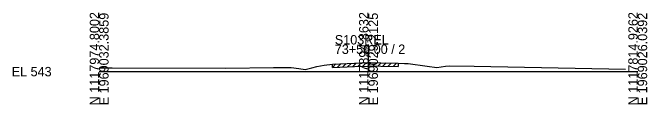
# Model space of a CAD drawing. Extents: x -26 to 163, y -10 to 24518.
# Drawn here: x -25.7 to 162.8, y 21990.3 to 22017.5 of the extents above; entities that cross this region are included whole.
import ezdxf

# ---------------------------------------------------------------- set-up
doc = ezdxf.new("R2010")
doc.units = 0
for name, color, linetype in [('RD_GPK_XS_Cell', 7, 'Continuous'), ('RD_XS_ExGround', 7, 'Continuous'), ('RD_XS_ExPaveRet', 7, 'Continuous'), ('RD_XS_TX_Elev_EX', 7, 'Continuous')]:
    doc.layers.add(name, color=color, linetype=linetype)

msp = doc.modelspace()

# ---------------------------------------------------------------- linework, layer by layer
at = {"layer": 'RD_GPK_XS_Cell'}
for p, q in [((80, 22000), (80, 22008.06)), ((0, 22000), (80, 22000)), ((80, 22000), (160, 22000))]:
    msp.add_line(p, q, dxfattribs=at)
at = {"layer": 'RD_XS_ExGround'}
msp.add_lwpolyline([(0, 22001.12), (3.84, 22001.13), (37.61, 22001.07), (51.79, 22001.2), (57, 22001.21), (59.27, 22000.93), (61.17, 22000.65), (63.13, 22001.14), (64.68, 22001.57), (66.82, 22001.89), (69.3, 22002.25), (75.84, 22002.5), (80, 22002.67), (80.5, 22002.69), (83.72, 22002.61), (88.78, 22002.52), (90.68, 22002.46), (91.83, 22002.42), (97.47, 22001.61), (100.33, 22001.2), (102.91, 22001.58), (104.22, 22001.74), (111.39, 22001.61), (156.35, 22000.78)], dxfattribs=at)
at = {"layer": 'RD_XS_ExPaveRet'}
for p, q in [((69.3, 22001.25), (70.34, 22002.29)), ((69.3, 22001.25), (69.3, 22002.25)), ((70.8, 22001.31), (71.84, 22002.35)), ((72.3, 22001.37), (73.34, 22002.41)), ((73.8, 22001.42), (74.84, 22002.46)), ((75.3, 22001.48), (76.34, 22002.52)), ((76.8, 22001.54), (77.84, 22002.58)), ((78.3, 22001.6), (79.34, 22002.64)), ((79.8, 22001.66), (80.82, 22002.68)), ((81.3, 22001.67), (82.28, 22002.64)), ((82.8, 22001.63), (83.78, 22002.61)), ((84.3, 22001.6), (85.28, 22002.58)), ((85.8, 22001.57), (86.78, 22002.56)), ((87.3, 22001.55), (88.28, 22002.53)), ((88.78, 22002.52), (88.78, 22001.52)), ((69.3, 22001.25), (75.84, 22001.5)), ((75.84, 22001.5), (80, 22001.67)), ((80, 22001.67), (80.5, 22001.69)), ((80.5, 22001.69), (83.72, 22001.61)), ((83.72, 22001.61), (88.78, 22001.52))]:
    msp.add_line(p, q, dxfattribs=at)

# ---------------------------------------------------------------- texts
at = {"layer": 'RD_GPK_XS_Cell'}
for s, p in [('N 1117974.8002', (0, 21990)), ('E 1969032.3859', (2.8, 21990)), ('N 1117894.8632', (80, 21990)), ('E 1969029.2125', (82.8, 21990)), ('N 1117814.9262', (160, 21990)), ('E 1969026.0392', (162.8, 21990))]:
    msp.add_text(s, height=2.8, rotation=90, dxfattribs=at).set_placement(p)
for s, p in [('S103REL', (70, 22008.06)), ('73+50.00 / 2', (70, 22005.26)), ('EL 543', (-26, 21998.6))]:
    msp.add_text(s, height=2.8, dxfattribs=at).set_placement(p)
at = {"layer": 'RD_XS_TX_Elev_EX'}
msp.add_text('545.67', height=0.8, rotation=90, dxfattribs=at).set_placement((79.9, 22004.67))

doc.saveas('drawing.dxf')
